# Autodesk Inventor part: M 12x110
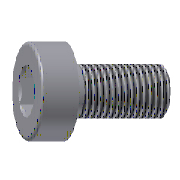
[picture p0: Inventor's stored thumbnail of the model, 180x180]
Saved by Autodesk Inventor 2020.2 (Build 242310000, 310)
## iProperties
IsCustomPart: 0
Manager: www.cadconsulting.pl
Company: Fabian Stasiak CAD Consulting
Created: 2014-02
Part Number: M 12x110
Material: Stal, miękka
Description: Socket Head Cap Screw DIN 912 - 12.9
Document SubType Name: Modeling
Designer: F.Stasiak
Standard Revision: 1
Manufacturer: DME
Language: pl-PL
Size Designation: 12x110
Categories: <MemberInstance><Categories><Category DisplayName="Forma wtryskowa" InternalName="349578f2-f4d4-4954-8c09-8e99297a61c0" Mnemonic="MOLD"><Category DisplayName="C
Mass: 0.133121 g
Surface Area: 2.01441 cm^2
Volume: 0.133121 cm^3
Density: 7.85 g/cm^3
Appearance: Częściowo polerowana
Catalog Web Link: www.expertbooks.pl
Author: F.Stasiak
Subject: Zbiór ćwiczeń. Autodesk Inventor 2020. Kurs Professional
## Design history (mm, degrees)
sketch "Sketch1"
  geometry: L1 (0, -134.4)-(0, 36.4) reference; L2 (5.774, 12)-(9, 12); L3 (9, 12)-(9, 0); L4 (9, 0)-(6, 0); L5 (6, 0)-(6, -110); L6 (6, -110)-(0, -110); L7 (0, 2.996)-(0, -110); L8 (0, 2.996)-(5, 6); L9 (5, 6)-(5, 11.226); L10 (5, 11.226)-(5.774, 12); 1 further point
  constraints: 18 end point, 4 vertical, 3 horizontal, 2 point on line
  dimensions: "d0" = 18 diameter of L3 L1 (= dk); "d1" = 12 distance between parallel lines of L4 L2 (= k); "d2" = 12 diameter of L5 L1 (= d); "d3" = 110 distance between parallel lines of L6 L4 (= L); "d4" = 59 deg angle of L1 L8; "d5" = 45 deg angle of L1 L10; "d6" = 10 diameter of L9 L1 (= sw); "d7" = 11.54701 diameter of L2.start L1 (= 1.1547 x sw); "d8" = 6 distance from line of L8.end L2 (= t)
revolve "Revolution1" sketch "Sketch1" stored, may be unused: angle "d44" = 90 deg
sketch "Sketch2"
  geometry: L1 (0, 5.774)-(5, 2.887); L2 (5, 2.887)-(5, -2.887); L3 (5, -2.887)-(0, -5.774); L4 (0, -5.774)-(-5, -2.887); L5 (-5, -2.887)-(-5, 2.887); L6 (-5, 2.887)-(0, 5.774); 3 further points
  constraints: 12 end point, 2 vertical alignment, 1 coincident, 14 other
extrude "Extrusion1" cut sketch "Sketch2" taper "d9" = 0 deg; stored distance "d45" = 10
thread "Thread1" dims "d10" = 28 (= b), "d11" = 0
chamfer "Chamfer1" distance "d12" = 0.875 (= 0.5 x P); stored, may be unused: second distance "d50" = 2, angle "d51" = 45 deg
fillet "Fillet1" dims "d13" = 0.875 (= 0.5 x P)
body "Solid1"
other parameters: "d" = 12 [user parameter; used in 1 equation term], "L" = 110 [user parameter; used in 1 equation term], "dk" = 18 [user parameter; used in 1 equation term], "b" = 28 [user parameter; used in 1 equation term], "k" = 12 [user parameter; used in 1 equation term], "sw" = 10 [user parameter; used in 2 equation terms], "t" = 6 [user parameter; used in 1 equation term], "P" = 1.75 [user parameter; used in 2 equation terms], "d14" = 0, "d15" = 0, "d55" = 0
